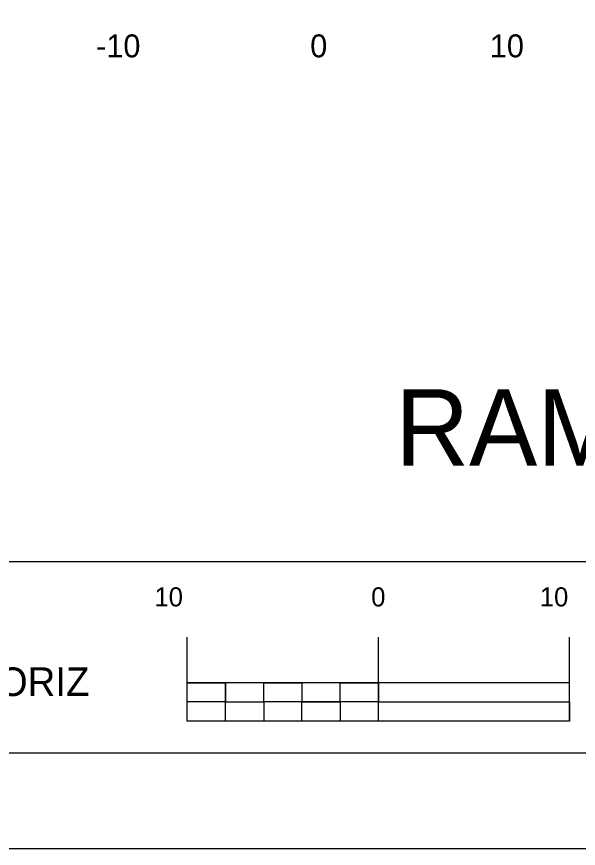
# Model space of a CAD drawing. Extents: x 1797809 to 2198143, y 249608 to 1237864.
# Drawn here: x 2195097 to 2195126.39, y 1237118.04 to 1237161.58 of the extents above; entities that cross this region are included whole.
import ezdxf

# ---------------------------------------------------------------- set-up
doc = ezdxf.new("R2010")
doc.units = 0
for name, color, linetype in [('10', 7, 'Continuous'), ('GSCOLORFILL', 7, 'Continuous'), ('GSDIMS', 7, 'Continuous'), ('GSSHT', 7, 'Continuous'), ('Level 33', 7, 'Continuous'), ('Level 45', 7, 'Continuous')]:
    doc.layers.add(name, color=color, linetype=linetype)

msp = doc.modelspace()

# ---------------------------------------------------------------- linework, layer by layer
at = {"layer": 'GSCOLORFILL'}
msp.add_lwpolyline([(2194870.363, 1237123.036), (2195192.863, 1237123.036), (2195192.863, 1237333.036), (2194870.363, 1237333.036)], close=True, dxfattribs=at)
at = {"layer": 'GSDIMS'}
for p, q in [((2195105.928, 1237124.7), (2195105.928, 1237129.1)), ((2195115.928, 1237124.7), (2195115.928, 1237129.1)), ((2195115.928, 1237124.7), (2195115.928, 1237129.1)), ((2195115.928, 1237124.7), (2195115.928, 1237129.1)), ((2195125.928, 1237124.7), (2195125.928, 1237129.1)), ((2195125.928, 1237126.7), (2195105.928, 1237126.7)), ((2195107.928, 1237125.7), (2195107.928, 1237126.7)), ((2195107.928, 1237125.7), (2195107.928, 1237126.7)), ((2195115.928, 1237125.7), (2195115.928, 1237126.7)), ((2195115.928, 1237125.7), (2195115.928, 1237126.7)), ((2195115.928, 1237125.7), (2195115.928, 1237126.7)), ((2195115.928, 1237125.7), (2195111.928, 1237125.7)), ((2195125.928, 1237124.7), (2195125.928, 1237125.7)), ((2195125.928, 1237124.7), (2195125.928, 1237125.7)), ((2195125.928, 1237124.7), (2195125.928, 1237125.7)), ((2195125.928, 1237124.7), (2195105.928, 1237124.7))]:
    msp.add_line(p, q, dxfattribs=at)
for points in [[(2195105.928, 1237126.7), (2195107.928, 1237126.7), (2195107.928, 1237125.7), (2195105.928, 1237125.7)], [(2195109.928, 1237126.7), (2195111.928, 1237126.7), (2195111.928, 1237125.7), (2195109.928, 1237125.7)], [(2195113.928, 1237126.7), (2195115.928, 1237126.7), (2195115.928, 1237125.7), (2195113.928, 1237125.7)], [(2195107.928, 1237125.7), (2195109.928, 1237125.7), (2195109.928, 1237124.7), (2195107.928, 1237124.7)], [(2195111.928, 1237125.7), (2195113.928, 1237125.7), (2195113.928, 1237124.7), (2195111.928, 1237124.7)], [(2195115.928, 1237125.7), (2195125.928, 1237125.7), (2195125.928, 1237124.7), (2195115.928, 1237124.7)]]:
    msp.add_lwpolyline(points, close=True, dxfattribs=at)
at = {"layer": 'GSSHT'}
msp.add_lwpolyline([(2194857.863, 1237118.036), (2195197.863, 1237118.036), (2195197.863, 1237338.036), (2194857.863, 1237338.036)], close=True, dxfattribs=at)
at = {"layer": 'Level 45'}
msp.add_lwpolyline([(2194882.86, 1237133.046), (2195182.86, 1237133.046), (2195182.86, 1237323.046), (2194882.86, 1237323.046)], close=True, dxfattribs=at)

# ---------------------------------------------------------------- texts
at = {"layer": '10'}
for s, p in [('-10', (2195101.157, 1237159.446)), ('0', (2195112.36, 1237159.446)), ('10', (2195121.76, 1237159.446))]:
    msp.add_text(s, height=1.2, dxfattribs=at).set_placement(p)
at = {"layer": 'GSDIMS'}
for s, height, p in [(' 10', 0.9991, (2195103.843, 1237130.7)), ('0', 1, (2195115.554, 1237130.7)), ('0', 1, (2195115.554, 1237130.7)), ('0', 1, (2195115.554, 1237130.7)), (' 10', 0.9991, (2195124.009, 1237130.7)), ('HORIZ', 1.4994, (2195094.566, 1237126.008))]:
    msp.add_text(s, height=height, rotation=0.0572, dxfattribs=at).set_placement(p)
at = {"layer": 'Level 33'}
msp.add_text('RAMP E', height=3.9977, rotation=360, dxfattribs=at).set_placement((2195116.815, 1237138.073))

doc.saveas('drawing.dxf')
